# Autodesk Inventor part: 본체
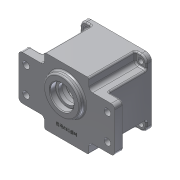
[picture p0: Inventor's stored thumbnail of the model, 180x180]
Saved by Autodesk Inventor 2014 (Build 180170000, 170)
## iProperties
Created: 2014-12
Part Number: 본체
Material: 알루미늄 6061
Document SubType Name: Modeling
Designer: MYHOME
Density: 2.71 g/cm^3
Appearance: 알루미늄 - 평지
Mass: 705.361 g
Surface Area: 672.962 cm^2
Volume: 260.281 cm^3
Author: MYHOME
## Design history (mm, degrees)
sketch "스케치2"
  geometry: L1 (-45, -45)-(45, -45); L2 (45, -45)-(45, 45); L3 (45, 45)-(-45, 45); L4 (-45, 45)-(-45, -45); L5 (-45, -45)-(45, 45); L6 (45, -45)-(-45, 45); 1 further point
  constraints: 12 end point, 2 midpoint, 2 parallel, 1 horizontal, 1 perpendicular
  dimensions: "d0" = 90 distance of L2.end L3.end; "d1" = 90 distance of L1.end L2.end
extrude "돌출1" new body sketch "스케치2" distance "d2" = 70; taper "d3" = 0 deg
sketch "스케치3"
  geometry: L1 (-65, -30)-(65, -30); L2 (65, -30)-(65, 30); L3 (65, 30)-(-65, 30); L4 (-65, 30)-(-65, -30); L5 (-65, -30)-(65, 30); L6 (65, -30)-(-65, 30); 1 further point
  constraints: 12 end point, 2 midpoint, 2 parallel, 1 horizontal, 1 perpendicular
  dimensions: "d4" = 130 distance of L2.end L3.end; "d5" = 60 distance of L1.end L2.end
extrude "돌출2" join sketch "스케치3" distance "d6" = 12; taper "d7" = 0 deg
sketch "스케치4"
  geometry: L1 (45, 30)-(45, 45) reference; L2 (45, 45)-(-45, 45) reference; L3 (-45, 45)-(-45, 30) reference; L4 (-45, -30)-(-45, -45) reference; L5 (-45, -45)-(45, -45) reference; L6 (-45, 45)-(-30, 45); L7 (-30, 45)-(-30, 30); L8 (-30, 30)-(-45, 30); L9 (-45, 30)-(-45, 45); L10 (45, 45)-(30, 45); L11 (30, 45)-(30, 30); L12 (30, 30)-(45, 30); L13 (45, 30)-(45, 45); L14 (45, -45)-(30, -45); L15 (30, -45)-(30, -30); L16 (30, -30)-(45, -30); L17 (45, -30)-(45, -45); L18 (-45, -45)-(-30, -45); L19 (-30, -45)-(-30, -30); L20 (-30, -30)-(-45, -30); L21 (-45, -30)-(-45, -45); 1 further point
  constraints: 32 end point, 8 parallel, 4 horizontal, 4 perpendicular
  dimensions: "d8" = 15 distance between parallel lines of L3 L7; "d9" = 15 distance between parallel lines of L2 L8 (= d8); "d10" = 15 distance between parallel lines of L1 L11 (= d8); "d11" = 15 distance between parallel lines of L12 L2 (= d8); "d12" = 15 distance between parallel lines of L17 L15 (= d8); "d13" = 15 distance between parallel lines of L5 L16 (= d8); "d14" = 15 distance between parallel lines of L5 L20 (= d8); "d15" = 15 distance between parallel lines of L19 L4 (= d8)
extrude "돌출3" cut sketch "스케치4" distance "d16" = 63; taper "d17" = 0 deg
fillet "모깎기-8" dims "d18" = 8
fillet "모깎기-5" dims "d19" = 5
sketch "스케치5"
  geometry: L1 (-37, -37)-(37, -37); L2 (37, -37)-(37, 37); L3 (37, 37)-(-37, 37); L4 (-37, 37)-(-37, -37); L5 (-37, -37)-(37, 37); L6 (37, -37)-(-37, 37); 7 further points
  constraints: 12 end point, 5 coincident, 3 midpoint, 2 parallel, 1 horizontal, 1 perpendicular
  dimensions: "d20" = 74 distance of L2.end L3.end; "d21" = 74 distance of L1.end L2.end
hole "구멍1" sketch "스케치5" at (-37, 37), (37, 37), (37, -37), (-37, -37) diameter "d22" = 7; stored, may be unused: countersink angle "d26" = 90 deg, drill point angle "d28" = 118 deg; dims "d23" = 6, "d24" = 4, "d25" = 2, "d27" = 8
sketch "스케치6"
  geometry: L1 (-55, -17.5)-(55, -17.5); L2 (55, -17.5)-(55, 17.5); L3 (55, 17.5)-(-55, 17.5); L4 (-55, 17.5)-(-55, -17.5); L5 (-55, -17.5)-(55, 17.5); L6 (55, -17.5)-(-55, 17.5); 5 further points
  constraints: 12 end point, 4 coincident, 2 midpoint, 2 parallel, 1 horizontal, 1 perpendicular
  dimensions: "d29" = 110 distance of L2.end L3.end; "d30" = 35 distance of L1.end L2.end
hole "구멍2" sketch "스케치6" at (-55, 17.5), (-55, -17.5), (55, -17.5), (55, 17.5) diameter "d31" = 9; stored, may be unused: countersink angle "d35" = 90 deg, drill point angle "d37" = 118 deg; dims "d32" = 6, "d33" = 4, "d34" = 2, "d36" = 8
fillet "모깎기3" dims "d38" = 2
sketch "스케치7"
  geometry: C1 r 25 at (0, 11); 1 further point
  constraints: 1 centre point, 1 vertical alignment
  dimensions: "d39" = 50 diameter of C1; "d40" = 11 distance of point (0, 0) C1.centre
extrude "돌출4" join sketch "스케치7" distance "d41" = 7; taper "d42" = 0 deg
fillet "모깎기4" dims "d43" = 2
sketch "스케치8"
  geometry: C1 r 40 at (0, 0); 1 further point
  constraints: 1 centre point, 1 coincident
  dimensions: "d44" = 40 radius of C1
extrude "돌출5" cut sketch "스케치8" distance "d45" = 9; taper "d46" = 0 deg
sketch "스케치9"
  geometry: C1 r 40 at (0, 0) reference; C2 r 39 at (0, 0)
  constraints: 1 centre point, 1 coincident
  dimensions: "d47" = 78 diameter of C2
extrude "돌출6" cut sketch "스케치9" distance "d48" = 52; taper "d49" = 0 deg
sketch "스케치10" dims "d50" = 70
  geometry: L1 (24.749, 24.749)-(-24.749, -24.749); L2 (-24.749, 24.749)-(24.749, -24.749); L3 (-35, 0)-(35, 0); A1 r 4 centre (24.749, 24.749) between (21.809, 27.462) and (27.462, 21.809); A2 r 4 centre (-24.749, 24.749) between (-27.462, 21.809) and (-21.809, 27.462); A3 r 4 centre (-24.749, -24.749) between (-21.809, -27.462) and (-27.462, -21.809); A4 r 4 centre (24.749, -24.749) between (27.462, -21.809) and (21.809, -27.462); A5 r 3.5 centre (19.238, -29.836) between (21.134, -32.777) and (21.762, -27.412); A6 r 3.5 centre (29.836, -19.238) between (27.412, -21.762) and (32.777, -21.134); A7 r 3.5 centre (29.836, 19.238) between (32.777, 21.134) and (27.412, 21.762); A8 r 3.5 centre (19.238, 29.836) between (21.762, 27.412) and (21.134, 32.777); A9 r 3.5 centre (-19.238, 29.836) between (-21.134, 32.777) and (-21.762, 27.412); A10 r 3.5 centre (-29.836, 19.238) between (-27.412, 21.762) and (-32.777, 21.134); A11 r 3.5 centre (-29.836, -19.238) between (-32.777, -21.134) and (-27.412, -21.762); A12 r 3.5 centre (-19.238, -29.836) between (-21.762, -27.412) and (-21.134, -32.777); 5 further points
  constraints: 32 point on circle, 12 centre point, 8 tangent, 7 equal radius, 6 coincident, 6 end point, 4 midpoint, 1 horizontal, 36 other
  dimensions: "d51" = 45 deg angle of L1 L3; "d52" = 90 deg angle of L1 L2; "d53" = 8 diameter of A1; "d54" = 8 diameter of A2; "d55" = 8 diameter of A3; "d56" = 8 diameter of A4; "d57" = 7 diameter of A12
extrude "돌출7" join sketch "스케치10" distance "d58" = 52; taper "d59" = 0 deg
sketch "스케치11"
  geometry: A1 r 4 centre (24.749, -24.749) between (27.462, -21.809) and (21.809, -27.462) reference; A2 r 4 centre (-24.749, -24.749) between (-21.809, -27.462) and (-27.462, -21.809) reference; A3 r 4 centre (-24.749, 24.749) between (-27.462, 21.809) and (-21.809, 27.462) reference; A4 r 4 centre (24.749, 24.749) between (21.809, 27.462) and (27.462, 21.809) reference; 4 further points
  constraints: 4 coincident
hole "구멍3" sketch "스케치11" at (-24.749, 24.749), (24.749, 24.749), (24.749, -24.749), (-24.749, -24.749) diameter "d60" = 3.459; stored, may be unused: countersink angle "d64" = 90 deg, drill point angle "d66" = 118 deg; dims "d61" = 12, "d62" = 4, "d63" = 2, "d65" = 15
sketch "스케치12"
  geometry: A1 r 39 centre (0, 0) between (32.777, -21.134) and (32.777, 21.134) reference; A2 r 39 centre (0, 0) between (-32.777, 21.134) and (-32.777, -21.134) reference; A3 r 20.5 centre (0, -11) between (-7.402, 8.117) and (7.402, 8.117); A4 r 14 centre (0, 20) between (7.402, 8.117) and (-7.402, 8.117)
  constraints: 4 point on circle, 2 centre point, 2 vertical alignment
  dimensions: "d67" = 41 diameter of A3; "d68" = 28 diameter of A4; "d69" = 11 distance of A1.centre A3.centre; "d70" = 20 distance of A1.centre A4.centre
extrude "돌출8" join sketch "스케치12" distance "d71" = 7; taper "d72" = 0 deg
fillet "모깎기5" dims "d73" = 3
fillet "모깎기6" dims "d74" = 2
sketch "스케치13"
  geometry: C1 r 17.5 at (0, -11); A1 r 20.5 centre (0, -11) between (-11.115, 6.225) and (11.115, 6.225) reference; 1 further point
  constraints: 1 centre point, 1 coincident
  dimensions: "d75" = 35 diameter of C1
extrude "돌출9" cut sketch "스케치13" distance "d76" = 10; taper "d77" = 0 deg
sketch "스케치14"
  geometry: C1 r 17.5 at (0, 0) reference; C2 r 12.5 at (0, 0); 1 further point
  constraints: 1 centre point, 1 coincident
  dimensions: "d78" = 25 diameter of C2
extrude "돌출10" cut sketch "스케치14" distance "d79" = 5; taper "d80" = 0 deg
sketch "스케치15"
  geometry: C1 r 23 at (0, 0) reference; C2 r 16 at (0, 0); 1 further point
  constraints: 1 centre point, 1 coincident
  dimensions: "d81" = 32 diameter of C2
extrude "돌출11" cut sketch "스케치15" distance "d82" = 8; taper "d83" = 0 deg
chamfer "모따기1" distance "d84" = 1; stored, may be unused: second distance "d85" = 2, angle "d86" = 45 deg
fillet "모깎기7" dims "d87" = 0.3
sketch "스케치16"
  geometry: C1 r 11 at (0, 20); A1 r 14 centre (0, 20) between (10.493, 10.732) and (-10.493, 10.732) reference; 1 further point
  constraints: 1 centre point, 1 coincident
  dimensions: "d88" = 22 diameter of C1
extrude "돌출12" cut sketch "스케치16" distance "d89" = 7; taper "d90" = 0 deg
sketch "스케치17"
  geometry: C1 r 11 at (0, 0) reference; C2 r 9.5 at (0, 0); 1 further point
  constraints: 1 centre point, 1 coincident
  dimensions: "d91" = 19 diameter of C2
extrude "돌출13" cut sketch "스케치17" distance "d92" = 1; taper "d93" = 0 deg
fillet "모깎기8" dims "d94" = 2
fillet "모깎기9" dims "d95" = 0.3
fillet "모깎기10" dims "d96" = 2
chamfer "모따기2" distance "d97" = 1; stored, may be unused: second distance "d98" = 2, angle "d99" = 45 deg
sketch "스케치18"
  geometry: L1 (-28, -45)-(28, -45) reference; C1 r 27 at (0, 11) reference; 2 further points
  constraints: 1 vertical alignment, 1 other
  dimensions: "d100" = 15 distance from line of L1 point (0, -30)
feature "엠보싱1" sketch "스케치18" dims "d0" = 90, "d1" = 90, "d101" = 0.5, "d102" = 0
node "솔리드1"
